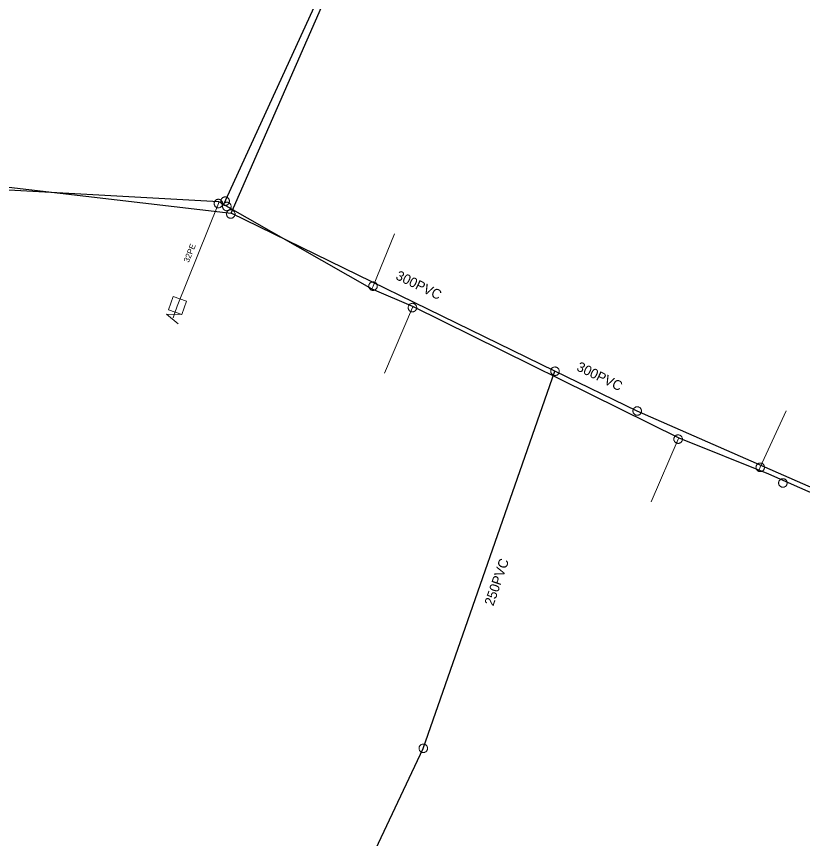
# Model space of a CAD drawing. Extents: x -741806 to -738704, y -1059275 to -1055387.
# Drawn here: x -740647.7 to -740567.1, y -1058134.3 to -1058050 of the extents above; entities that cross this region are included whole.
import ezdxf

# ---------------------------------------------------------------- set-up
doc = ezdxf.new("R2010")
doc.units = 0
doc.header["$LTSCALE"] = 0.4
for name, color, linetype, lineweight in [('2', 7, 'Continuous', 25), ('21', 7, 'Continuous', 13), ('3', 7, 'Continuous', 13), ('51', 7, 'Continuous', 13), ('52', 7, 'Continuous', 25), ('60', 7, 'Continuous', 13)]:
    doc.layers.add(name, color=color, linetype=linetype, lineweight=lineweight)
doc.layers.add('5', color=7, linetype='Continuous')
doc.layers.add('54', color=7, linetype='Continuous')

msp = doc.modelspace()

# ---------------------------------------------------------------- linework, layer by layer
at = {"layer": '2'}
for p, q in [((-740584.07, -1058090.47), (-740592.5, -1058086.389)), ((-740538.35, -1058110.56), (-740584.07, -1058090.47))]:
    msp.add_line(p, q, dxfattribs=at)
for points in [[(-740592.5, -1058086.389), (-740625.71, -1058070.179), (-740593.93, -1057997.629)], [(-740824.89, -1058051.27), (-740778.35, -1058055.46), (-740728.07, -1058059.94), (-740708.829, -1058061.48), (-740678.949, -1058063.95), (-740625.71, -1058070.179)], [(-740583.26, -1058185.25), (-740598.636, -1058178.666), (-740610.313, -1058173.665), (-740625.809, -1058167.03), (-740606.009, -1058125.064), (-740592.5, -1058086.389)]]:
    msp.add_lwpolyline(points, dxfattribs=at)
at = {"layer": '21'}
for points in [[(-740626.965, -1058069.033), (-740627.02, -1058069.19), (-740631.25, -1058079.72), (-740631.527, -1058080.499), (-740631.654, -1058080.922)], [(-740611.274, -1058077.928), (-740611.16, -1058077.659), (-740608.947, -1058072.284)], [(-740607.048, -1058079.747), (-740607.12, -1058079.86), (-740609.973, -1058086.591)], [(-740571.566, -1058096.51), (-740571.449, -1058096.24), (-740568.795, -1058090.463)], [(-740579.795, -1058093.213), (-740579.87, -1058093.35), (-740582.627, -1058099.791)]]:
    msp.add_lwpolyline(points, dxfattribs=at)
at = {"layer": '3'}
for points in [[(-740625.317, -1058070.31), (-740625.315, -1058070.265), (-740625.317, -1058070.22), (-740625.324, -1058070.174), (-740625.336, -1058070.13), (-740625.352, -1058070.087), (-740625.373, -1058070.046), (-740625.398, -1058070.008), (-740625.426, -1058069.971), (-740625.459, -1058069.94), (-740625.494, -1058069.911), (-740625.533, -1058069.885), (-740625.574, -1058069.864), (-740625.616, -1058069.848), (-740625.66, -1058069.835), (-740625.705, -1058069.829), (-740625.751, -1058069.826), (-740625.797, -1058069.829), (-740625.842, -1058069.835), (-740625.887, -1058069.847), (-740625.93, -1058069.864), (-740625.97, -1058069.884), (-740626.008, -1058069.908), (-740626.044, -1058069.938), (-740626.077, -1058069.969), (-740626.106, -1058070.005), (-740626.13, -1058070.044), (-740626.152, -1058070.084), (-740626.168, -1058070.127), (-740626.18, -1058070.171), (-740626.187, -1058070.217), (-740626.19, -1058070.262), (-740626.188, -1058070.307), (-740626.181, -1058070.353), (-740626.169, -1058070.398), (-740626.153, -1058070.44), (-740626.132, -1058070.481), (-740626.107, -1058070.519), (-740626.078, -1058070.556), (-740626.046, -1058070.587), (-740626.011, -1058070.616), (-740625.973, -1058070.642), (-740625.932, -1058070.663), (-740625.889, -1058070.68), (-740625.845, -1058070.692), (-740625.8, -1058070.698), (-740625.754, -1058070.701), (-740625.708, -1058070.699), (-740625.663, -1058070.692), (-740625.619, -1058070.68), (-740625.576, -1058070.663), (-740625.535, -1058070.643), (-740625.496, -1058070.619), (-740625.461, -1058070.589), (-740625.428, -1058070.558), (-740625.399, -1058070.522), (-740625.374, -1058070.483), (-740625.354, -1058070.443), (-740625.337, -1058070.4), (-740625.325, -1058070.356), (-740625.317, -1058070.311)], [(-740592.894, -1058086.197), (-740592.91, -1058086.239), (-740592.924, -1058086.283), (-740592.933, -1058086.328), (-740592.936, -1058086.373), (-740592.935, -1058086.419), (-740592.93, -1058086.465), (-740592.919, -1058086.509), (-740592.905, -1058086.553), (-740592.884, -1058086.594), (-740592.861, -1058086.633), (-740592.833, -1058086.67), (-740592.802, -1058086.704), (-740592.767, -1058086.733), (-740592.73, -1058086.76), (-740592.69, -1058086.781), (-740592.647, -1058086.8), (-740592.603, -1058086.812), (-740592.559, -1058086.821), (-740592.513, -1058086.825), (-740592.467, -1058086.824), (-740592.422, -1058086.818), (-740592.378, -1058086.808), (-740592.334, -1058086.792), (-740592.293, -1058086.774), (-740592.253, -1058086.749), (-740592.217, -1058086.721), (-740592.184, -1058086.691), (-740592.153, -1058086.656), (-740592.127, -1058086.618), (-740592.105, -1058086.578), (-740592.088, -1058086.536), (-740592.074, -1058086.493), (-740592.066, -1058086.447), (-740592.062, -1058086.401), (-740592.063, -1058086.356), (-740592.068, -1058086.31), (-740592.079, -1058086.266), (-740592.094, -1058086.222), (-740592.114, -1058086.181), (-740592.137, -1058086.142), (-740592.165, -1058086.106), (-740592.196, -1058086.072), (-740592.23, -1058086.042), (-740592.268, -1058086.016), (-740592.308, -1058085.994), (-740592.351, -1058085.976), (-740592.394, -1058085.962), (-740592.439, -1058085.954), (-740592.485, -1058085.95), (-740592.531, -1058085.951), (-740592.576, -1058085.957), (-740592.621, -1058085.967), (-740592.664, -1058085.983), (-740592.706, -1058086.002), (-740592.745, -1058086.026), (-740592.782, -1058086.054), (-740592.814, -1058086.084), (-740592.845, -1058086.12), (-740592.871, -1058086.157), (-740592.893, -1058086.196)], [(-740584.47, -1058090.293), (-740584.486, -1058090.335), (-740584.497, -1058090.379), (-740584.504, -1058090.425), (-740584.507, -1058090.47), (-740584.504, -1058090.516), (-740584.497, -1058090.562), (-740584.484, -1058090.606), (-740584.468, -1058090.649), (-740584.447, -1058090.689), (-740584.422, -1058090.727), (-740584.393, -1058090.763), (-740584.36, -1058090.796), (-740584.324, -1058090.823), (-740584.286, -1058090.849), (-740584.245, -1058090.869), (-740584.202, -1058090.886), (-740584.158, -1058090.897), (-740584.113, -1058090.904), (-740584.067, -1058090.906), (-740584.021, -1058090.903), (-740583.976, -1058090.896), (-740583.933, -1058090.884), (-740583.889, -1058090.867), (-740583.849, -1058090.847), (-740583.81, -1058090.821), (-740583.775, -1058090.792), (-740583.743, -1058090.76), (-740583.714, -1058090.724), (-740583.689, -1058090.685), (-740583.669, -1058090.644), (-740583.653, -1058090.602), (-740583.641, -1058090.558), (-740583.634, -1058090.512), (-740583.632, -1058090.466), (-740583.634, -1058090.421), (-740583.641, -1058090.375), (-740583.654, -1058090.332), (-740583.671, -1058090.288), (-740583.692, -1058090.248), (-740583.716, -1058090.21), (-740583.745, -1058090.174), (-740583.778, -1058090.142), (-740583.813, -1058090.113), (-740583.852, -1058090.088), (-740583.893, -1058090.068), (-740583.936, -1058090.051), (-740583.98, -1058090.04), (-740584.025, -1058090.033), (-740584.071, -1058090.031), (-740584.117, -1058090.034), (-740584.162, -1058090.042), (-740584.206, -1058090.053), (-740584.249, -1058090.07), (-740584.29, -1058090.09), (-740584.328, -1058090.116), (-740584.364, -1058090.145), (-740584.395, -1058090.177), (-740584.425, -1058090.214), (-740584.449, -1058090.252), (-740584.47, -1058090.292)], [(-740605.821, -1058124.668), (-740605.863, -1058124.651), (-740605.907, -1058124.638), (-740605.953, -1058124.63), (-740605.997, -1058124.626), (-740606.043, -1058124.628), (-740606.089, -1058124.634), (-740606.133, -1058124.645), (-740606.177, -1058124.66), (-740606.218, -1058124.681), (-740606.256, -1058124.704), (-740606.293, -1058124.732), (-740606.327, -1058124.764), (-740606.355, -1058124.799), (-740606.382, -1058124.836), (-740606.403, -1058124.877), (-740606.421, -1058124.92), (-740606.433, -1058124.964), (-740606.442, -1058125.008), (-740606.445, -1058125.054), (-740606.443, -1058125.1), (-740606.437, -1058125.146), (-740606.427, -1058125.189), (-740606.411, -1058125.233), (-740606.392, -1058125.274), (-740606.367, -1058125.313), (-740606.338, -1058125.349), (-740606.308, -1058125.382), (-740606.272, -1058125.412), (-740606.234, -1058125.438), (-740606.194, -1058125.459), (-740606.152, -1058125.477), (-740606.108, -1058125.49), (-740606.063, -1058125.498), (-740606.016, -1058125.501), (-740605.972, -1058125.5), (-740605.926, -1058125.494), (-740605.882, -1058125.483), (-740605.838, -1058125.467), (-740605.798, -1058125.447), (-740605.759, -1058125.424), (-740605.722, -1058125.395), (-740605.689, -1058125.364), (-740605.659, -1058125.329), (-740605.633, -1058125.291), (-740605.612, -1058125.251), (-740605.594, -1058125.208), (-740605.581, -1058125.164), (-740605.573, -1058125.12), (-740605.57, -1058125.073), (-740605.572, -1058125.027), (-740605.578, -1058124.982), (-740605.588, -1058124.938), (-740605.604, -1058124.895), (-740605.624, -1058124.854), (-740605.648, -1058124.814), (-740605.676, -1058124.778), (-740605.708, -1058124.746), (-740605.743, -1058124.715), (-740605.781, -1058124.69), (-740605.82, -1058124.668)]]:
    msp.add_lwpolyline(points, dxfattribs=at)
at = {"layer": '51'}
for points in [[(-740626.519, -1058069.341), (-740626.477, -1058069.359), (-740626.434, -1058069.373), (-740626.388, -1058069.382), (-740626.344, -1058069.386), (-740626.298, -1058069.386), (-740626.251, -1058069.381), (-740626.207, -1058069.37), (-740626.163, -1058069.356), (-740626.122, -1058069.337), (-740626.083, -1058069.314), (-740626.046, -1058069.286), (-740626.012, -1058069.255), (-740625.981, -1058069.221), (-740625.955, -1058069.184), (-740625.933, -1058069.144), (-740625.914, -1058069.102), (-740625.9, -1058069.058), (-740625.891, -1058069.014), (-740625.887, -1058068.968), (-740625.888, -1058068.922), (-740625.893, -1058068.876), (-740625.902, -1058068.832), (-740625.918, -1058068.788), (-740625.936, -1058068.747), (-740625.96, -1058068.707), (-740625.987, -1058068.67), (-740626.018, -1058068.637), (-740626.053, -1058068.606), (-740626.09, -1058068.58), (-740626.13, -1058068.557), (-740626.171, -1058068.539), (-740626.215, -1058068.526), (-740626.26, -1058068.516), (-740626.305, -1058068.512), (-740626.351, -1058068.512), (-740626.397, -1058068.517), (-740626.442, -1058068.528), (-740626.485, -1058068.542), (-740626.526, -1058068.562), (-740626.566, -1058068.584), (-740626.603, -1058068.612), (-740626.637, -1058068.643), (-740626.667, -1058068.677), (-740626.694, -1058068.714), (-740626.716, -1058068.754), (-740626.735, -1058068.796), (-740626.748, -1058068.84), (-740626.757, -1058068.884), (-740626.761, -1058068.931), (-740626.761, -1058068.977), (-740626.755, -1058069.022), (-740626.746, -1058069.066), (-740626.731, -1058069.11), (-740626.713, -1058069.151), (-740626.689, -1058069.191), (-740626.661, -1058069.228), (-740626.631, -1058069.261), (-740626.596, -1058069.292), (-740626.559, -1058069.318), (-740626.519, -1058069.34)], [(-740626.583, -1058069.19), (-740626.585, -1058069.145), (-740626.592, -1058069.1), (-740626.604, -1058069.055), (-740626.62, -1058069.013), (-740626.641, -1058068.972), (-740626.666, -1058068.933), (-740626.695, -1058068.898), (-740626.727, -1058068.865), (-740626.763, -1058068.837), (-740626.801, -1058068.812), (-740626.842, -1058068.791), (-740626.885, -1058068.774), (-740626.929, -1058068.762), (-740626.974, -1058068.755), (-740627.02, -1058068.753), (-740627.066, -1058068.755), (-740627.111, -1058068.762), (-740627.155, -1058068.774), (-740627.198, -1058068.791), (-740627.239, -1058068.812), (-740627.277, -1058068.837), (-740627.313, -1058068.865), (-740627.345, -1058068.898), (-740627.374, -1058068.933), (-740627.399, -1058068.972), (-740627.42, -1058069.013), (-740627.436, -1058069.055), (-740627.448, -1058069.1), (-740627.455, -1058069.145), (-740627.458, -1058069.191), (-740627.455, -1058069.236), (-740627.448, -1058069.281), (-740627.436, -1058069.326), (-740627.42, -1058069.368), (-740627.399, -1058069.409), (-740627.374, -1058069.448), (-740627.345, -1058069.483), (-740627.313, -1058069.516), (-740627.277, -1058069.544), (-740627.239, -1058069.569), (-740627.198, -1058069.59), (-740627.155, -1058069.607), (-740627.111, -1058069.618), (-740627.066, -1058069.626), (-740627.02, -1058069.628), (-740626.974, -1058069.626), (-740626.929, -1058069.618), (-740626.885, -1058069.607), (-740626.842, -1058069.59), (-740626.801, -1058069.569), (-740626.763, -1058069.544), (-740626.727, -1058069.516), (-740626.695, -1058069.483), (-740626.666, -1058069.448), (-740626.641, -1058069.409), (-740626.62, -1058069.368), (-740626.604, -1058069.326), (-740626.592, -1058069.281), (-740626.585, -1058069.236), (-740626.583, -1058069.191)], [(-740625.716, -1058069.504), (-740625.716, -1058069.459), (-740625.722, -1058069.413), (-740625.732, -1058069.368), (-740625.747, -1058069.326), (-740625.766, -1058069.284), (-740625.79, -1058069.244), (-740625.818, -1058069.208), (-740625.849, -1058069.174), (-740625.884, -1058069.145), (-740625.921, -1058069.119), (-740625.961, -1058069.096), (-740626.004, -1058069.078), (-740626.047, -1058069.064), (-740626.092, -1058069.056), (-740626.138, -1058069.052), (-740626.184, -1058069.053), (-740626.229, -1058069.058), (-740626.273, -1058069.069), (-740626.317, -1058069.084), (-740626.359, -1058069.104), (-740626.398, -1058069.128), (-740626.434, -1058069.154), (-740626.468, -1058069.186), (-740626.498, -1058069.22), (-740626.524, -1058069.258), (-740626.546, -1058069.299), (-740626.564, -1058069.34), (-740626.577, -1058069.385), (-740626.586, -1058069.429), (-740626.59, -1058069.475), (-740626.589, -1058069.52), (-740626.583, -1058069.566), (-740626.573, -1058069.611), (-740626.558, -1058069.653), (-740626.539, -1058069.695), (-740626.515, -1058069.735), (-740626.487, -1058069.771), (-740626.456, -1058069.805), (-740626.421, -1058069.834), (-740626.384, -1058069.86), (-740626.344, -1058069.883), (-740626.301, -1058069.901), (-740626.258, -1058069.914), (-740626.213, -1058069.923), (-740626.167, -1058069.927), (-740626.121, -1058069.926), (-740626.076, -1058069.92), (-740626.032, -1058069.91), (-740625.988, -1058069.895), (-740625.946, -1058069.875), (-740625.908, -1058069.851), (-740625.871, -1058069.825), (-740625.838, -1058069.793), (-740625.807, -1058069.759), (-740625.781, -1058069.721), (-740625.759, -1058069.68), (-740625.741, -1058069.639), (-740625.728, -1058069.594), (-740625.719, -1058069.55), (-740625.716, -1058069.505)], [(-740610.723, -1058077.659), (-740610.725, -1058077.614), (-740610.732, -1058077.569), (-740610.744, -1058077.524), (-740610.76, -1058077.482), (-740610.781, -1058077.441), (-740610.806, -1058077.402), (-740610.835, -1058077.367), (-740610.867, -1058077.334), (-740610.903, -1058077.306), (-740610.941, -1058077.281), (-740610.982, -1058077.26), (-740611.025, -1058077.243), (-740611.069, -1058077.231), (-740611.114, -1058077.224), (-740611.16, -1058077.222), (-740611.206, -1058077.224), (-740611.251, -1058077.231), (-740611.295, -1058077.243), (-740611.338, -1058077.26), (-740611.379, -1058077.281), (-740611.417, -1058077.306), (-740611.453, -1058077.334), (-740611.485, -1058077.367), (-740611.514, -1058077.402), (-740611.539, -1058077.441), (-740611.56, -1058077.482), (-740611.576, -1058077.524), (-740611.588, -1058077.569), (-740611.595, -1058077.614), (-740611.598, -1058077.66), (-740611.595, -1058077.705), (-740611.588, -1058077.75), (-740611.576, -1058077.795), (-740611.56, -1058077.837), (-740611.539, -1058077.878), (-740611.514, -1058077.917), (-740611.485, -1058077.952), (-740611.453, -1058077.985), (-740611.417, -1058078.013), (-740611.379, -1058078.038), (-740611.338, -1058078.059), (-740611.295, -1058078.076), (-740611.251, -1058078.087), (-740611.206, -1058078.095), (-740611.16, -1058078.097), (-740611.114, -1058078.095), (-740611.069, -1058078.087), (-740611.025, -1058078.076), (-740610.982, -1058078.059), (-740610.941, -1058078.038), (-740610.903, -1058078.013), (-740610.867, -1058077.985), (-740610.835, -1058077.952), (-740610.806, -1058077.917), (-740610.781, -1058077.878), (-740610.76, -1058077.837), (-740610.744, -1058077.795), (-740610.732, -1058077.75), (-740610.725, -1058077.705), (-740610.723, -1058077.66)], [(-740606.718, -1058080.033), (-740606.702, -1058079.991), (-740606.691, -1058079.947), (-740606.684, -1058079.901), (-740606.682, -1058079.856), (-740606.685, -1058079.81), (-740606.693, -1058079.764), (-740606.706, -1058079.72), (-740606.722, -1058079.677), (-740606.744, -1058079.637), (-740606.769, -1058079.599), (-740606.798, -1058079.564), (-740606.831, -1058079.531), (-740606.867, -1058079.503), (-740606.905, -1058079.479), (-740606.947, -1058079.459), (-740606.99, -1058079.442), (-740607.034, -1058079.431), (-740607.079, -1058079.424), (-740607.125, -1058079.423), (-740607.171, -1058079.426), (-740607.216, -1058079.434), (-740607.26, -1058079.446), (-740607.303, -1058079.463), (-740607.343, -1058079.484), (-740607.382, -1058079.51), (-740607.417, -1058079.539), (-740607.448, -1058079.571), (-740607.477, -1058079.608), (-740607.501, -1058079.647), (-740607.522, -1058079.688), (-740607.537, -1058079.73), (-740607.549, -1058079.774), (-740607.556, -1058079.82), (-740607.557, -1058079.865), (-740607.554, -1058079.911), (-740607.547, -1058079.957), (-740607.534, -1058080), (-740607.518, -1058080.043), (-740607.496, -1058080.083), (-740607.471, -1058080.121), (-740607.441, -1058080.157), (-740607.409, -1058080.19), (-740607.373, -1058080.217), (-740607.334, -1058080.242), (-740607.293, -1058080.262), (-740607.25, -1058080.279), (-740607.205, -1058080.289), (-740607.161, -1058080.296), (-740607.114, -1058080.298), (-740607.069, -1058080.295), (-740607.024, -1058080.287), (-740606.98, -1058080.275), (-740606.937, -1058080.258), (-740606.897, -1058080.237), (-740606.858, -1058080.211), (-740606.823, -1058080.182), (-740606.791, -1058080.149), (-740606.763, -1058080.113), (-740606.738, -1058080.074), (-740606.719, -1058080.034)], [(-740580.08, -1058093.733), (-740580.039, -1058093.752), (-740579.997, -1058093.768), (-740579.951, -1058093.779), (-740579.907, -1058093.785), (-740579.861, -1058093.786), (-740579.814, -1058093.783), (-740579.77, -1058093.775), (-740579.726, -1058093.762), (-740579.684, -1058093.744), (-740579.644, -1058093.723), (-740579.605, -1058093.697), (-740579.57, -1058093.667), (-740579.538, -1058093.635), (-740579.51, -1058093.598), (-740579.487, -1058093.559), (-740579.466, -1058093.518), (-740579.451, -1058093.475), (-740579.44, -1058093.431), (-740579.434, -1058093.385), (-740579.433, -1058093.339), (-740579.437, -1058093.293), (-740579.444, -1058093.248), (-740579.458, -1058093.204), (-740579.475, -1058093.162), (-740579.497, -1058093.121), (-740579.523, -1058093.083), (-740579.552, -1058093.049), (-740579.585, -1058093.017), (-740579.622, -1058092.989), (-740579.66, -1058092.965), (-740579.701, -1058092.946), (-740579.744, -1058092.93), (-740579.789, -1058092.919), (-740579.834, -1058092.913), (-740579.88, -1058092.912), (-740579.926, -1058092.915), (-740579.971, -1058092.923), (-740580.015, -1058092.936), (-740580.057, -1058092.954), (-740580.097, -1058092.975), (-740580.135, -1058093.001), (-740580.171, -1058093.031), (-740580.202, -1058093.064), (-740580.23, -1058093.1), (-740580.254, -1058093.139), (-740580.274, -1058093.18), (-740580.289, -1058093.224), (-740580.301, -1058093.267), (-740580.306, -1058093.313), (-740580.308, -1058093.359), (-740580.304, -1058093.405), (-740580.297, -1058093.45), (-740580.283, -1058093.494), (-740580.266, -1058093.536), (-740580.244, -1058093.577), (-740580.218, -1058093.615), (-740580.189, -1058093.649), (-740580.155, -1058093.681), (-740580.119, -1058093.709), (-740580.081, -1058093.732)], [(-740571.012, -1058096.24), (-740571.014, -1058096.195), (-740571.021, -1058096.15), (-740571.033, -1058096.105), (-740571.049, -1058096.063), (-740571.07, -1058096.022), (-740571.095, -1058095.983), (-740571.124, -1058095.948), (-740571.156, -1058095.915), (-740571.192, -1058095.887), (-740571.23, -1058095.862), (-740571.271, -1058095.841), (-740571.314, -1058095.824), (-740571.358, -1058095.812), (-740571.403, -1058095.805), (-740571.449, -1058095.803), (-740571.495, -1058095.805), (-740571.54, -1058095.812), (-740571.584, -1058095.824), (-740571.627, -1058095.841), (-740571.668, -1058095.862), (-740571.706, -1058095.887), (-740571.742, -1058095.915), (-740571.774, -1058095.948), (-740571.803, -1058095.983), (-740571.828, -1058096.022), (-740571.849, -1058096.063), (-740571.865, -1058096.105), (-740571.877, -1058096.15), (-740571.884, -1058096.195), (-740571.887, -1058096.241), (-740571.884, -1058096.286), (-740571.877, -1058096.331), (-740571.865, -1058096.376), (-740571.849, -1058096.418), (-740571.828, -1058096.459), (-740571.803, -1058096.498), (-740571.774, -1058096.533), (-740571.742, -1058096.566), (-740571.706, -1058096.594), (-740571.668, -1058096.619), (-740571.627, -1058096.64), (-740571.584, -1058096.657), (-740571.54, -1058096.668), (-740571.495, -1058096.676), (-740571.449, -1058096.678), (-740571.403, -1058096.676), (-740571.358, -1058096.668), (-740571.314, -1058096.657), (-740571.271, -1058096.64), (-740571.23, -1058096.619), (-740571.192, -1058096.594), (-740571.156, -1058096.566), (-740571.124, -1058096.533), (-740571.095, -1058096.498), (-740571.07, -1058096.459), (-740571.049, -1058096.418), (-740571.033, -1058096.376), (-740571.021, -1058096.331), (-740571.014, -1058096.286), (-740571.012, -1058096.241)], [(-740568.69, -1058097.842), (-740568.691, -1058097.797), (-740568.699, -1058097.752), (-740568.711, -1058097.707), (-740568.727, -1058097.665), (-740568.748, -1058097.624), (-740568.772, -1058097.585), (-740568.802, -1058097.55), (-740568.834, -1058097.517), (-740568.87, -1058097.489), (-740568.907, -1058097.464), (-740568.949, -1058097.443), (-740568.992, -1058097.426), (-740569.036, -1058097.414), (-740569.081, -1058097.407), (-740569.127, -1058097.405), (-740569.173, -1058097.407), (-740569.218, -1058097.414), (-740569.262, -1058097.426), (-740569.304, -1058097.443), (-740569.346, -1058097.464), (-740569.384, -1058097.489), (-740569.419, -1058097.517), (-740569.451, -1058097.55), (-740569.481, -1058097.585), (-740569.505, -1058097.624), (-740569.527, -1058097.665), (-740569.543, -1058097.707), (-740569.554, -1058097.752), (-740569.562, -1058097.797), (-740569.565, -1058097.843), (-740569.562, -1058097.888), (-740569.554, -1058097.933), (-740569.543, -1058097.978), (-740569.527, -1058098.02), (-740569.505, -1058098.061), (-740569.481, -1058098.1), (-740569.451, -1058098.135), (-740569.419, -1058098.168), (-740569.384, -1058098.196), (-740569.346, -1058098.221), (-740569.304, -1058098.242), (-740569.262, -1058098.259), (-740569.218, -1058098.27), (-740569.173, -1058098.278), (-740569.127, -1058098.28), (-740569.081, -1058098.278), (-740569.036, -1058098.27), (-740568.992, -1058098.259), (-740568.949, -1058098.242), (-740568.907, -1058098.221), (-740568.87, -1058098.196), (-740568.834, -1058098.168), (-740568.802, -1058098.135), (-740568.772, -1058098.1), (-740568.748, -1058098.061), (-740568.727, -1058098.02), (-740568.711, -1058097.978), (-740568.699, -1058097.933), (-740568.691, -1058097.888), (-740568.69, -1058097.843)]]:
    msp.add_lwpolyline(points, dxfattribs=at)
at = {"layer": '52'}
for points in [[(-740489.868, -1057679.99), (-740497.519, -1057704.287), (-740502.89, -1057727.946), (-740504.09, -1057731.52), (-740504.16, -1057731.78), (-740504.295, -1057732.394), (-740505.458, -1057737.884), (-740512.487, -1057766.415), (-740507.033, -1057770.061), (-740517.328, -1057816.22), (-740521.664, -1057829.6), (-740544.85, -1057893.509), (-740554.399, -1057919.446), (-740570.451, -1057950.712), (-740592.697, -1058007.398), (-740600.714, -1058010.487), (-740613.05, -1058039.97), (-740626.485, -1058069.3)], [(-740626.537, -1058069.271), (-740626.965, -1058069.033), (-740656.548, -1058067.382), (-740672.59, -1058065.485), (-740708.822, -1058062.591), (-740710.671, -1058062.095), (-740751.42, -1058058.46), (-740773.993, -1058056.467), (-740779.522, -1058055.831), (-740794.666, -1058054.688), (-740823.883, -1058052.338), (-740835.024, -1058060.166), (-740841.695, -1058066.003), (-740887.96, -1058170.041), (-740903.829, -1058207.8), (-740906.75, -1058213.899)], [(-740626.537, -1058069.271), (-740611.274, -1058077.928), (-740607.048, -1058079.747), (-740579.795, -1058093.213), (-740570.602, -1058096.897), (-740532.225, -1058113.83), (-740517.855, -1058120.051), (-740513.324, -1058122.253), (-740504.39, -1058126.338), (-740503.699, -1058126.483), (-740502.37, -1058127.033), (-740486.897, -1058134.004), (-740457.162, -1058146.413), (-740443.484, -1058152.384), (-740427.182, -1058159.244), (-740419.138, -1058162.291), (-740410.995, -1058165.443), (-740391.353, -1058175.139), (-740386.026, -1058178.196), (-740381.706, -1058180.966), (-740367.603, -1058204.507), (-740360.942, -1058216.102), (-740348.353, -1058239.253)]]:
    msp.add_lwpolyline(points, dxfattribs=at)
at = {"layer": '60'}
msp.add_lwpolyline([(-740631.655, -1058078.711), (-740630.288, -1058079.199), (-740630.775, -1058080.567), (-740632.143, -1058080.079)], close=True, dxfattribs=at)
msp.add_lwpolyline([(-740630.793, -1058080.567), (-740632.336, -1058080.542), (-740631.141, -1058081.542)], dxfattribs=at)

# ---------------------------------------------------------------- texts
at = {"layer": '5'}
for s, rotation, p in [('300PVC', 334, (-740608.919, -1058076.911)), ('300PVC', 334, (-740590.368, -1058086.264)), ('250PVC', 71, (-740598.826, -1058110.522))]:
    msp.add_text(s, height=1, rotation=rotation, dxfattribs=at).set_placement(p)
at = {"layer": '54'}
msp.add_text('32PE', height=0.6, rotation=68, dxfattribs=at).set_placement((-740630.056, -1058075.288))

doc.saveas('drawing.dxf')
